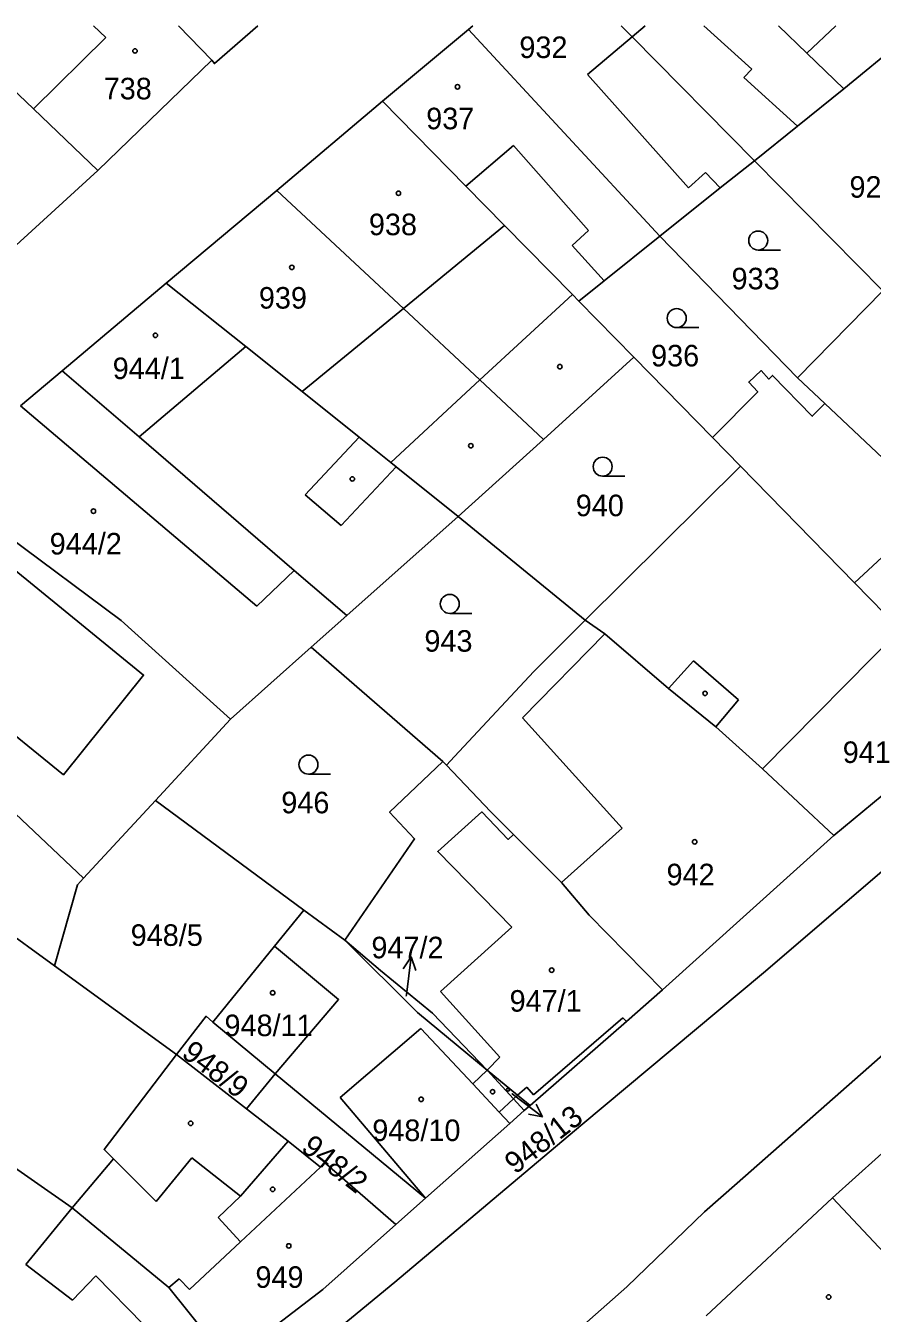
# Model space of a CAD drawing. Extents: x -600849 to -599899, y -1204328 to -1203436.
# Drawn here: x -600307 to -600240.2, y -1203539.8 to -1203438.2 of the extents above; entities that cross this region are included whole.
import ezdxf

# ---------------------------------------------------------------- set-up
doc = ezdxf.new("R2010")
doc.units = 0
for name, color, linetype in [('Vrstva 1', 7, 'Continuous'), ('Vrstva 2', 7, 'Continuous'), ('Vrstva 3', 7, 'Continuous'), ('Vrstva 4', 7, 'Continuous'), ('Vrstva 5', 7, 'Continuous'), ('Vrstva 7', 7, 'Continuous')]:
    doc.layers.add(name, color=color, linetype=linetype)

msp = doc.modelspace()

# ---------------------------------------------------------------- linework, layer by layer
at = {"layer": 'Vrstva 1'}
for p, q in [((-600292.31, -1203440.91), (-600294.94, -1203438.18)), ((-600272.07, -1203438.47), (-600278.85, -1203444.13)), ((-600271.73, -1203438.18), (-600272.07, -1203438.47)), ((-600272.07, -1203438.47), (-600256.98, -1203454.78)), ((-600236.43, -1203438.18), (-600242.46, -1203443.15)), ((-600301.32, -1203449.6), (-600292.31, -1203440.91)), ((-600278.85, -1203444.13), (-600287.18, -1203451.18)), ((-600249.52, -1203448.83), (-600239.38, -1203459.09)), ((-600312.03, -1203459.39), (-600301.32, -1203449.6)), ((-600287.18, -1203451.18), (-600295.91, -1203458.48)), ((-600256.98, -1203454.78), (-600246.12, -1203465.97)), ((-600295.91, -1203458.48), (-600304.12, -1203465.4)), ((-600246.12, -1203465.97), (-600239.38, -1203459.09)), ((-600263.37, -1203459.9), (-600259.03, -1203464.34)), ((-600266.16, -1203470.82), (-600259.03, -1203464.34)), ((-600259.03, -1203464.34), (-600252.82, -1203470.68)), ((-600304.12, -1203465.4), (-600307.41, -1203468.17)), ((-600246.12, -1203465.97), (-600243.97, -1203468)), ((-600272.89, -1203476.89), (-600266.16, -1203470.82)), ((-600252.82, -1203470.68), (-600250.61, -1203472.94)), ((-600262.88, -1203485.08), (-600250.61, -1203472.94)), ((-600272.89, -1203476.89), (-600281.68, -1203484.71)), ((-600272.89, -1203476.89), (-600262.88, -1203485.08)), ((-600281.68, -1203484.71), (-600284.48, -1203487.2)), ((-600290.85, -1203492.89), (-600284.48, -1203487.2)), ((-600284.48, -1203487.2), (-600274.1, -1203496.23)), ((-600320.3, -1203488.59), (-600302.45, -1203505.43)), ((-600243.26, -1203502.07), (-600231.59, -1203492.38)), ((-600296.77, -1203499.31), (-600290.85, -1203492.89)), ((-600274.1, -1203496.23), (-600273.82, -1203496.53)), ((-600302.45, -1203505.43), (-600296.77, -1203499.31)), ((-600296.77, -1203499.31), (-600285.05, -1203507.96)), ((-600256.76, -1203514.25), (-600243.26, -1203502.07)), ((-600312.92, -1203506.4), (-600304.74, -1203512.36)), ((-600287.37, -1203510.81), (-600285.05, -1203507.96)), ((-600285.05, -1203507.96), (-600281.83, -1203510.33)), ((-600292.23, -1203516.79), (-600287.37, -1203510.81)), ((-600304.74, -1203512.36), (-600295.1, -1203519.34)), ((-600292.23, -1203516.79), (-600287.32, -1203520.88)), ((-600289.59, -1203523.64), (-600295.1, -1203519.34)), ((-600231.04, -1203519.56), (-600243.36, -1203530.67)), ((-600287.32, -1203520.88), (-600289.59, -1203523.64)), ((-600275.47, -1203530.68), (-600287.32, -1203520.88)), ((-600267.22, -1203523.37), (-600267.67, -1203523.77)), ((-600310.81, -1203526.22), (-600303.33, -1203531.45)), ((-600283.42, -1203527.86), (-600277.81, -1203532.75)), ((-600277.81, -1203532.75), (-600275.47, -1203530.68)), ((-600243.36, -1203530.67), (-600253.33, -1203539.97))]:
    msp.add_line(p, q, dxfattribs=at)
for points in [[(-600301.32, -1203449.6), (-600306.4, -1203444.75), (-600313.28, -1203438.18)], [(-600292.31, -1203440.91), (-600292.12, -1203441.17), (-600288.7, -1203438.18)], [(-600260.04, -1203438.18), (-600259.17, -1203439.06), (-600249.52, -1203448.83)], [(-600247.62, -1203438.18), (-600245.38, -1203440.34), (-600242.46, -1203443.15)], [(-600242.46, -1203443.15), (-600246.13, -1203446.1), (-600249.52, -1203448.83)], [(-600278.85, -1203444.13), (-600272.28, -1203450.83), (-600269.24, -1203453.93), (-600263.88, -1203459.38), (-600263.37, -1203459.9)], [(-600256.98, -1203454.78), (-600252.21, -1203450.98), (-600249.52, -1203448.83)], [(-600287.18, -1203451.18), (-600277.21, -1203460.49), (-600271.17, -1203466.13), (-600266.16, -1203470.82)], [(-600256.98, -1203454.78), (-600261.38, -1203458.3), (-600263.37, -1203459.9)], [(-600295.91, -1203458.48), (-600289.65, -1203463.48), (-600285.19, -1203467.05), (-600280.69, -1203470.65), (-600278.2, -1203472.64), (-600277.77, -1203472.98), (-600272.89, -1203476.89)], [(-600304.12, -1203465.4), (-600298.04, -1203470.63), (-600285.82, -1203481.15), (-600281.68, -1203484.71)], [(-600243.97, -1203468), (-600244.96, -1203468.99), (-600248.08, -1203465.77), (-600248.39, -1203466.06), (-600248.99, -1203465.39), (-600249.96, -1203466.3), (-600249.26, -1203467.07), (-600252.82, -1203470.68)], [(-600243.97, -1203468), (-600231.2, -1203480.01), (-600223.8, -1203486.97)], [(-600314.07, -1203473.38), (-600309.26, -1203477.69), (-600308.45, -1203478.42), (-600299.47, -1203485.12), (-600290.85, -1203492.89)], [(-600250.61, -1203472.94), (-600241.62, -1203482.13), (-600238.01, -1203485.82), (-600231.59, -1203492.38)], [(-600253.46, -1203531.77), (-600250.87, -1203529.49), (-600236.72, -1203517.04), (-600231.61, -1203512.54), (-600215.86, -1203498.68), (-600205.6, -1203489.66), (-600193.53, -1203478.84), (-600187.44, -1203473.68)], [(-600262.88, -1203485.08), (-600266.92, -1203489.14), (-600273.19, -1203495.84), (-600273.82, -1203496.53)], [(-600262.88, -1203485.08), (-600261.33, -1203486.16), (-600256.29, -1203490.46), (-600252.57, -1203493.5), (-600248.89, -1203496.82), (-600243.26, -1203502.07)], [(-600281.83, -1203510.33), (-600276.33, -1203502.34), (-600278.3, -1203500.23), (-600274.1, -1203496.23)], [(-600273.82, -1203496.53), (-600270.34, -1203500.18), (-600268.52, -1203502), (-600264.74, -1203505.77), (-600262.55, -1203508.36), (-600256.76, -1203514.25)], [(-600468.32, -1203708.8), (-600459.02, -1203700.91), (-600447.7, -1203689.53), (-600398.8, -1203640.57), (-600381.76, -1203623.36), (-600376.64, -1203618.38), (-600366.85, -1203610.56), (-600358.79, -1203604.64), (-600335.27, -1203586.75), (-600326.92, -1203580.15), (-600315.47, -1203571.41), (-600313.87, -1203569.96), (-600309.19, -1203565.44), (-600307.64, -1203563.87), (-600297.75, -1203553.71), (-600294.09, -1203550.64), (-600277.89, -1203537.3), (-600263.22, -1203524.94), (-600248.8, -1203512.9), (-600231.21, -1203497.85)], [(-600304.74, -1203512.36), (-600302.91, -1203505.96), (-600302.45, -1203505.43)], [(-600287.37, -1203510.81), (-600282.32, -1203515.02), (-600287.32, -1203520.88)], [(-600270.59, -1203520.59), (-600276.1, -1203516.03), (-600281.83, -1203510.33)], [(-600281.83, -1203510.33), (-600279.02, -1203512.71), (-600274.92, -1203516.08), (-600270.59, -1203520.59)], [(-600256.76, -1203514.25), (-600259.62, -1203516.75), (-600267.22, -1203523.37)], [(-600295.1, -1203519.34), (-600292.78, -1203516.33), (-600292.23, -1203516.79)], [(-600295.1, -1203519.34), (-600300.82, -1203526.84), (-600300.07, -1203527.59), (-600303.33, -1203531.45)], [(-600267.67, -1203523.77), (-600268.51, -1203522.85), (-600270.59, -1203520.59)], [(-600270.59, -1203520.59), (-600268.2, -1203522.57), (-600267.22, -1203523.37)], [(-600289.59, -1203523.64), (-600286.29, -1203526.2), (-600283.76, -1203528.23), (-600283.42, -1203527.86)], [(-600275.47, -1203530.68), (-600268.82, -1203524.79), (-600267.67, -1203523.77)], [(-600235.89, -1203538.76), (-600237.69, -1203536.71), (-600243.36, -1203530.67)], [(-600516.74, -1203754.05), (-600500.93, -1203742.85), (-600482.23, -1203729.97), (-600472.33, -1203722.55), (-600463.46, -1203715.87), (-600456.83, -1203710.5), (-600450.71, -1203706.1), (-600424.21, -1203680.79), (-600406.92, -1203664.19), (-600381.77, -1203639.93), (-600378.09, -1203636.25), (-600365.25, -1203624.15), (-600362.86, -1203622.3), (-600356.33, -1203617.3), (-600346.34, -1203609.78), (-600334.21, -1203600.46), (-600309.35, -1203581.63), (-600259.57, -1203537.67), (-600253.46, -1203531.77)], [(-600303.33, -1203531.45), (-600295.71, -1203537.74), (-600291, -1203543.59)], [(-600291, -1203543.59), (-600283.56, -1203537.9), (-600277.81, -1203532.75)]]:
    msp.add_lwpolyline(points, dxfattribs=at)
at = {"layer": 'Vrstva 3'}
for p, q in [((-600249.22, -1203455.88), (-600247.47, -1203455.88)), ((-600255.65, -1203462), (-600253.9, -1203462)), ((-600261.49, -1203473.72), (-600259.74, -1203473.72)), ((-600273.55, -1203484.55), (-600271.8, -1203484.55)), ((-600284.7, -1203497.23), (-600282.95, -1203497.23))]:
    msp.add_line(p, q, dxfattribs=at)
for centre in [(-600249.22, -1203455.13), (-600255.65, -1203461.25), (-600261.49, -1203472.97), (-600273.55, -1203483.8), (-600284.7, -1203496.48)]:
    msp.add_circle(centre, 0.75, dxfattribs=at)
at = {"layer": 'Vrstva 4'}
for p, q in [((-600300.68, -1203439.11), (-600301.65, -1203438.18)), ((-600259.17, -1203439.06), (-600258.13, -1203438.18)), ((-600253.52, -1203438.18), (-600249.72, -1203441.62)), ((-600243.1, -1203438.18), (-600245.38, -1203440.34)), ((-600300.68, -1203439.11), (-600306.4, -1203444.75)), ((-600262.69, -1203442.02), (-600259.17, -1203439.06)), ((-600250.35, -1203442.26), (-600249.72, -1203441.62)), ((-600262.69, -1203442.02), (-600254.71, -1203450.98)), ((-600250.35, -1203442.26), (-600246.13, -1203446.1)), ((-600268.53, -1203447.63), (-600272.28, -1203450.83)), ((-600268.53, -1203447.63), (-600262.61, -1203454.35)), ((-600254.71, -1203450.98), (-600253.37, -1203449.75)), ((-600253.37, -1203449.75), (-600252.21, -1203450.98)), ((-600277.21, -1203460.49), (-600269.24, -1203453.93)), ((-600262.61, -1203454.35), (-600263.9, -1203455.52)), ((-600263.9, -1203455.52), (-600261.38, -1203458.3)), ((-600271.17, -1203466.13), (-600263.88, -1203459.38)), ((-600285.19, -1203467.05), (-600277.21, -1203460.49)), ((-600289.65, -1203463.48), (-600298.04, -1203470.63)), ((-600278.2, -1203472.64), (-600271.17, -1203466.13)), ((-600307.41, -1203468.17), (-600288.78, -1203483.98)), ((-600284.95, -1203475.2), (-600280.69, -1203470.65)), ((-600277.77, -1203472.98), (-600282.13, -1203477.6)), ((-600282.13, -1203477.6), (-600284.95, -1203475.2)), ((-600241.62, -1203482.13), (-600238.74, -1203479.45)), ((-600288.78, -1203483.98), (-600285.82, -1203481.15)), ((-600267.81, -1203492.8), (-600261.33, -1203486.16)), ((-600248.89, -1203496.82), (-600238.01, -1203485.82)), ((-600256.29, -1203490.46), (-600254.33, -1203488.3)), ((-600254.33, -1203488.3), (-600250.77, -1203491.38)), ((-600250.77, -1203491.38), (-600252.57, -1203493.5)), ((-600259.96, -1203501.48), (-600267.81, -1203492.8)), ((-600264.74, -1203505.77), (-600259.96, -1203501.48)), ((-600274.28, -1203514.39), (-600268.66, -1203509.31)), ((-600269.6, -1203519.57), (-600274.28, -1203514.39)), ((-600259.89, -1203516.46), (-600266.94, -1203522.52)), ((-600259.62, -1203516.75), (-600259.89, -1203516.46)), ((-600275.84, -1203517.29), (-600282.2, -1203522.73)), ((-600275.84, -1203517.29), (-600271.74, -1203521.66)), ((-600269.6, -1203519.57), (-600270.59, -1203520.59)), ((-600270.59, -1203520.59), (-600271.74, -1203521.66)), ((-600271.74, -1203521.66), (-600269.65, -1203523.9)), ((-600268.2, -1203522.57), (-600267.48, -1203521.92)), ((-600266.94, -1203522.52), (-600267.48, -1203521.92)), ((-600282.2, -1203522.73), (-600275.47, -1203530.68)), ((-600269.65, -1203523.9), (-600268.51, -1203522.85)), ((-600268.51, -1203522.85), (-600268.2, -1203522.57)), ((-600269.65, -1203523.9), (-600268.82, -1203524.79)), ((-600286.29, -1203526.2), (-600290.07, -1203530.52)), ((-600300.07, -1203527.59), (-600296.72, -1203530.95)), ((-600296.72, -1203530.95), (-600293.89, -1203527.51)), ((-600293.89, -1203527.51), (-600290.07, -1203530.52)), ((-600290.06, -1203534.12), (-600283.76, -1203528.23)), ((-600290.07, -1203530.52), (-600291.82, -1203532.22)), ((-600303.33, -1203531.45), (-600306.98, -1203535.92)), ((-600291.82, -1203532.22), (-600290.06, -1203534.12)), ((-600294.09, -1203537.9), (-600290.06, -1203534.12)), ((-600306.98, -1203535.92), (-600303.32, -1203538.73)), ((-600303.32, -1203538.73), (-600301.47, -1203536.82)), ((-600301.47, -1203536.82), (-600297.71, -1203540.64)), ((-600294.89, -1203537.06), (-600295.71, -1203537.74)), ((-600294.09, -1203537.9), (-600294.89, -1203537.06))]:
    msp.add_line(p, q, dxfattribs=at)
for points in [[(-600318.17, -1203477.26), (-600312.63, -1203481.97), (-600316.73, -1203486.97), (-600304.03, -1203497.28), (-600297.71, -1203489.41), (-600310.38, -1203479.08), (-600309.26, -1203477.69)], [(-600268.66, -1203509.31), (-600274.5, -1203503.33), (-600271.01, -1203500.21), (-600268.94, -1203502.38), (-600268.52, -1203502)]]:
    msp.add_lwpolyline(points, dxfattribs=at)
at = {"layer": 'Vrstva 5'}
for centre, radius in [((-600298.38, -1203440.17), 0.175), ((-600272.94, -1203443), 0.175), ((-600277.6, -1203451.4), 0.175), ((-600286.01, -1203457.25), 0.175), ((-600296.77, -1203462.61), 0.175), ((-600264.87, -1203465.08), 0.175), ((-600271.89, -1203471.32), 0.175), ((-600281.24, -1203473.94), 0.175), ((-600301.66, -1203476.48), 0.175), ((-600253.41, -1203490.86), 0.175), ((-600254.23, -1203502.57), 0.175), ((-600265.51, -1203512.7), 0.175), ((-600287.52, -1203514.48), 0.175), ((-600270.17, -1203522.29), 0.175), ((-600268.96, -1203522.13), 0.117), ((-600275.81, -1203522.89), 0.175), ((-600293.99, -1203524.78), 0.175), ((-600287.52, -1203529.99), 0.175), ((-600286.25, -1203534.45), 0.175), ((-600243.66, -1203538.48), 0.175)]:
    msp.add_circle(centre, radius, dxfattribs=at)
at = {"layer": 'Vrstva 7'}
for p, q in [((-600276.6, -1203511.65), (-600277.22, -1203512.58)), ((-600276.97, -1203514.63), (-600276.6, -1203511.65)), ((-600276.6, -1203511.65), (-600276.23, -1203512.71)), ((-600276.99, -1203514.76), (-600276.97, -1203514.63)), ((-600268.66, -1203522.45), (-600268.63, -1203522.46)), ((-600268.63, -1203522.46), (-600266.23, -1203524.27)), ((-600266.23, -1203524.27), (-600267.33, -1203524.06)), ((-600266.23, -1203524.27), (-600266.73, -1203523.26))]:
    msp.add_line(p, q, dxfattribs=at)

# ---------------------------------------------------------------- texts
at = {"layer": 'Vrstva 2'}
for s, p in [('932', (-600268.06, -1203440.73)), ('738', (-600300.85, -1203443.99)), ('937', (-600275.41, -1203446.35)), ('929/2', (-600242.02, -1203451.75)), ('938', (-600279.93, -1203454.71)), ('933', (-600251.32, -1203458.98)), ('939', (-600288.61, -1203460.5)), ('944/1', (-600300.14, -1203466.06)), ('936', (-600257.67, -1203465.06)), ('940', (-600263.61, -1203476.88)), ('944/2', (-600305.11, -1203479.9)), ('943', (-600275.55, -1203487.57)), ('941', (-600242.55, -1203496.35)), ('946', (-600286.84, -1203500.32)), ('942', (-600256.45, -1203506)), ('948/5', (-600298.72, -1203510.78)), ('947/2', (-600279.73, -1203511.76)), ('947/1', (-600268.83, -1203515.97)), ('948/11', (-600291.32, -1203517.9)), ('948/10', (-600279.66, -1203526.18)), ('949', (-600288.88, -1203537.76))]:
    msp.add_text(s, height=1.7, dxfattribs=at).set_placement(p)
for s, rotation, p in [('948/9', 323, (-600294.8, -1203519.47)), ('948/13', 38, (-600268.38, -1203528.85)), ('948/2', 322, (-600285.37, -1203526.89))]:
    msp.add_text(s, height=1.7, rotation=rotation, dxfattribs=at).set_placement(p)

doc.saveas('drawing.dxf')
